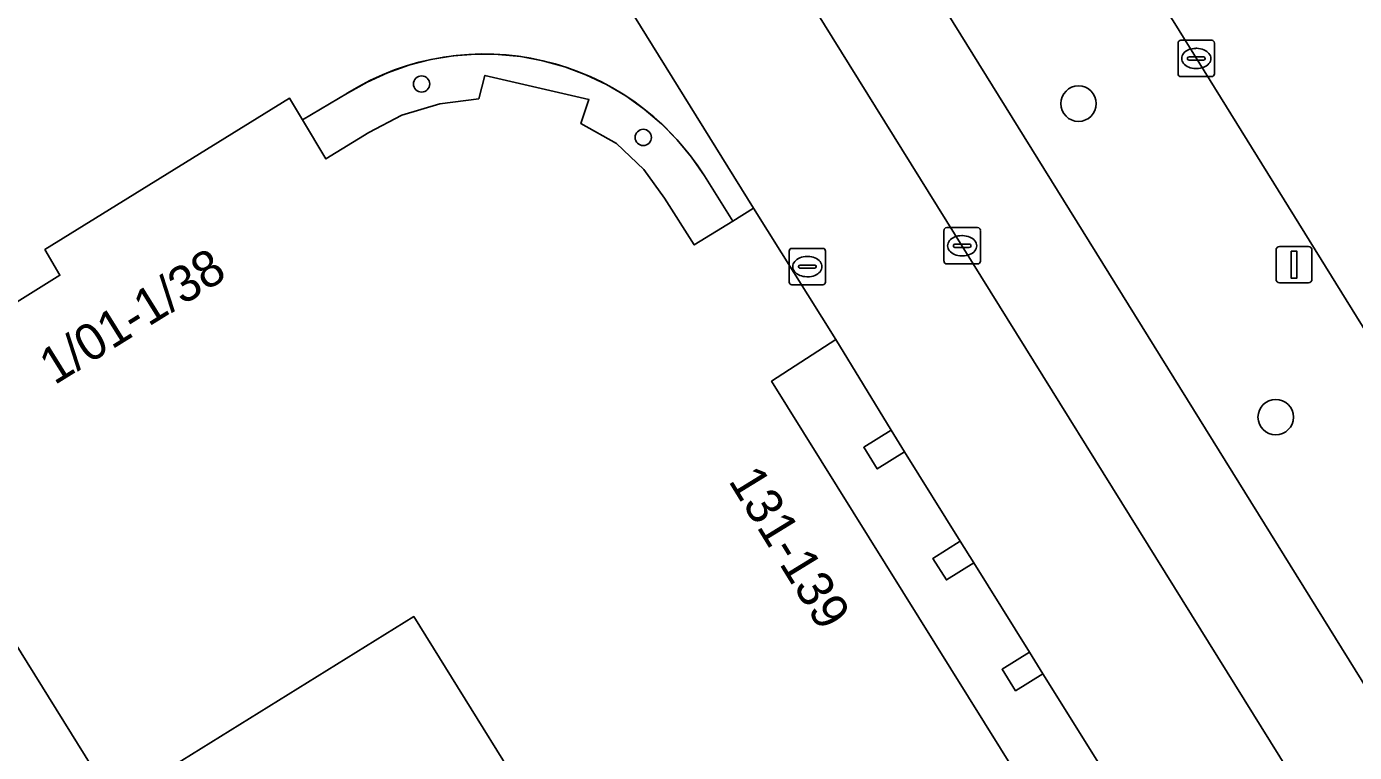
# Model space of a CAD drawing. Extents: x 160304 to 160955, y 383684 to 384161.
# Drawn here: x 160743.18 to 160779.74, y 384074.11 to 384094.11 of the extents above; entities that cross this region are included whole.
import ezdxf

# ---------------------------------------------------------------- set-up
doc = ezdxf.new("R2010")
doc.units = 0
for name, color, linetype in [('IMGEO_Boom', 7, 'Continuous'), ('IMGEO_Erf', 7, 'Continuous'), ('IMGEO_Fietspad_open', 7, 'Continuous'), ('IMGEO_Groenvoorziening', 7, 'Continuous'), ('IMGEO_Haag', 7, 'Continuous'), ('IMGEO_Kolk', 7, 'Continuous'), ('IMGEO_Lichtmast', 7, 'Continuous'), ('IMGEO_Pand', 7, 'Continuous'), ('IMGEO_Pand_nummerreeks', 7, 'Continuous'), ('IMGEO_Pand_overbouw', 7, 'Continuous'), ('IMGEO_Parkeervlak_open', 7, 'Continuous'), ('IMGEO_Rijbaan_lokaal_gesloten', 7, 'Continuous'), ('IMGEO_Rioolput', 7, 'Continuous'), ('IMGEO_Voetpad_open', 7, 'Continuous')]:
    doc.layers.add(name, color=color, linetype=linetype)

msp = doc.modelspace()

# ---------------------------------------------------------------- linework, layer by layer
at = {"layer": 'IMGEO_Boom'}
for centre in [(160772.146, 384091.984), (160777.574, 384083.35)]:
    msp.add_circle(centre, 0.489, dxfattribs=at)
at = {"layer": 'IMGEO_Erf'}
for points in [[(160755.635, 384092.12), (160755.804, 384092.759), (160758.666, 384092.1), (160758.445, 384091.436), (160759.426, 384090.887), (160760.175, 384090.166), (160760.744, 384089.38), (160761.566, 384088.092), (160762.626, 384088.748), (160761.845, 384089.993)], [(160752.016, 384092.274), (160750.778, 384091.538), (160751.426, 384090.46), (160752.611, 384091.192), (160753.516, 384091.667), (160754.563, 384091.979), (160755.635, 384092.12)], [(160772.696, 384073.832), (160771.166, 384076.282), (160770.412, 384075.813), (160770.041, 384076.406), (160770.795, 384076.876), (160769.262, 384079.336), (160768.508, 384078.866), (160768.136, 384079.46), (160768.891, 384079.93), (160767.358, 384082.395), (160766.603, 384081.925), (160766.233, 384082.519), (160766.987, 384082.989), (160765.464, 384085.483), (160763.696, 384084.339), (160772.246, 384070.611)], [(160762.238, 384064.34), (160753.846, 384077.856), (160745.599, 384072.736)]]:
    msp.add_lwpolyline(points, dxfattribs=at)
for centre, radius, start, end in [((160755.787, 384086.208), 7.143, 31.9983, 121.8712), ((160754.059, 384092.525), 0.224, 0, 180), ((160754.059, 384092.525), 0.224, 180, 0), ((160760.162, 384091.052), 0.224, 0, 180), ((160760.162, 384091.052), 0.224, 180, 0)]:
    msp.add_arc(centre, radius, start, end, dxfattribs=at)
at = {"layer": 'IMGEO_Fietspad_open'}
for points in [[(160751.873, 384115.337), (160755.715, 384109.34), (160755.728, 384109.32), (160788.518, 384056.578), (160823.662, 384000), (160830.017, 383989.77), (160839.554, 383974.387)], [(160842.328, 383975.591), (160832.842, 383990.888), (160827.177, 384000), (160814.975, 384019.629), (160813.456, 384022.072), (160805.259, 384035.309), (160768.526, 384094.486), (160764.835, 384100.432), (160758.942, 384109.926), (160757.079, 384112.871)]]:
    msp.add_lwpolyline(points, dxfattribs=at)
at = {"layer": 'IMGEO_Groenvoorziening'}
for points in [[(160786.766, 384074.88), (160774.746, 384094.262), (160772.522, 384097.674), (160768.7, 384103.329)], [(160768.526, 384094.486), (160805.259, 384035.309), (160806.841, 384036.335), (160804.538, 384041.052), (160799.23, 384052.134), (160793.098, 384064.312)]]:
    msp.add_lwpolyline(points, dxfattribs=at)
at = {"layer": 'IMGEO_Haag'}
for points in [[(160790.082, 384069.549), (160786.766, 384074.88), (160774.746, 384094.262), (160772.522, 384097.674), (160768.7, 384103.329)], [(160768.526, 384094.486), (160805.259, 384035.309), (160806.841, 384036.335), (160804.538, 384041.052), (160799.23, 384052.134), (160793.098, 384064.312)]]:
    msp.add_lwpolyline(points, dxfattribs=at)
at = {"layer": 'IMGEO_Kolk'}
for p, q in [((160774.885, 384092.801), (160774.885, 384093.653)), ((160774.96, 384093.727), (160775.812, 384093.727)), ((160775.373, 384093.507), (160775.398, 384093.507)), ((160775.886, 384093.653), (160775.886, 384092.801)), ((160775.144, 384093.221), (160775.144, 384093.233)), ((160775.582, 384093.184), (160775.184, 384093.184)), ((160775.187, 384093.27), (160775.585, 384093.27)), ((160775.628, 384093.233), (160775.628, 384093.221)), ((160775.812, 384092.727), (160774.96, 384092.727)), ((160775.396, 384092.947), (160775.371, 384092.947)), ((160768.441, 384087.642), (160768.441, 384088.494)), ((160768.516, 384088.568), (160769.368, 384088.568)), ((160768.929, 384088.348), (160768.954, 384088.348)), ((160769.442, 384088.494), (160769.442, 384087.642)), ((160768.7, 384088.062), (160768.7, 384088.074)), ((160769.138, 384088.025), (160768.74, 384088.025)), ((160768.743, 384088.111), (160769.141, 384088.111)), ((160769.184, 384088.074), (160769.184, 384088.062)), ((160768.952, 384087.788), (160768.927, 384087.788)), ((160769.368, 384087.568), (160768.516, 384087.568))]:
    msp.add_line(p, q, dxfattribs=at)
for points in [[(160774.885, 384092.801), (160774.885, 384093.653)], [(160774.96, 384093.727), (160775.812, 384093.727)], [(160775.886, 384093.653), (160775.886, 384092.801)], [(160775.812, 384092.727), (160774.96, 384092.727)], [(160768.441, 384087.642), (160768.441, 384088.494)], [(160768.516, 384088.568), (160769.368, 384088.568)], [(160769.442, 384088.494), (160769.442, 384087.642)], [(160769.368, 384087.568), (160768.516, 384087.568)]]:
    msp.add_lwpolyline(points, dxfattribs=at)
for centre, radius, start, end in [((160774.962, 384093.651), 0.0765, 91.552, 178.448), ((160774.962, 384093.651), 0.0765, 91.552, 178.448), ((160775.81, 384093.651), 0.0765, 1.552, 88.448), ((160775.81, 384093.651), 0.0765, 1.552, 88.448), ((160775.184, 384093.23), 0.0403, 85.8775, 175.7526), ((160775.181, 384093.22), 0.0366, 178.938, 274.7102), ((160775.585, 384093.227), 0.043, 264.8664, 352.4533), ((160775.589, 384093.232), 0.0386, 1.7309, 96.639), ((160774.962, 384092.803), 0.0765, 181.552, 268.448), ((160774.962, 384092.803), 0.0765, 181.552, 268.448), ((160775.81, 384092.803), 0.0765, 271.552, 358.448), ((160775.81, 384092.803), 0.0765, 271.552, 358.448), ((160768.518, 384088.492), 0.0765, 91.552, 178.448), ((160768.518, 384088.492), 0.0765, 91.552, 178.448), ((160769.366, 384088.492), 0.0765, 1.552, 88.448), ((160769.366, 384088.492), 0.0765, 1.552, 88.448), ((160768.74, 384088.071), 0.0403, 85.8775, 175.7526), ((160768.737, 384088.061), 0.0366, 178.938, 274.7102), ((160769.141, 384088.068), 0.043, 264.8664, 352.4533), ((160769.145, 384088.073), 0.0386, 1.7309, 96.639), ((160768.518, 384087.644), 0.0765, 181.552, 268.448), ((160768.518, 384087.644), 0.0765, 181.552, 268.448), ((160769.366, 384087.644), 0.0765, 271.552, 358.448), ((160769.366, 384087.644), 0.0765, 271.552, 358.448)]:
    msp.add_arc(centre, radius, start, end, dxfattribs=at)
for centre, major_axis, ratio, start_param, end_param in [((160775.372, 384093.227), (-0.387, 0.002), 0.722429, 4.712389, 7.853982), ((160775.397, 384093.227), (-0.39, 0.002), 0.717154, 1.570796, 4.712389), ((160768.928, 384088.068), (-0.387, 0.002), 0.722429, 4.712389, 7.853982), ((160768.953, 384088.068), (-0.39, 0.002), 0.717154, 1.570796, 4.712389)]:
    msp.add_ellipse(centre, major_axis=major_axis, ratio=ratio, start_param=start_param, end_param=end_param, dxfattribs=at)
at = {"layer": 'IMGEO_Lichtmast'}
for p, q in [((160777.682, 384088.048), (160778.472, 384088.048)), ((160778.472, 384088.048), (160777.682, 384088.048)), ((160777.582, 384087.148), (160777.582, 384087.948)), ((160777.582, 384087.948), (160777.582, 384087.148)), ((160778.572, 384087.948), (160778.572, 384087.148)), ((160778.572, 384087.148), (160778.572, 384087.948)), ((160778.472, 384087.048), (160777.682, 384087.048)), ((160777.682, 384087.048), (160778.472, 384087.048))]:
    msp.add_line(p, q, dxfattribs=at)
msp.add_lwpolyline([(160778.002, 384087.923), (160778.152, 384087.923), (160778.152, 384087.173), (160778.002, 384087.173), (160778.002, 384087.923)], dxfattribs=at)
for centre, start, end in [((160777.682, 384087.948), 90, 180), ((160777.682, 384087.948), 90, 180), ((160778.472, 384087.948), 0, 90), ((160778.472, 384087.948), 360, 90), ((160777.682, 384087.148), 180, 270), ((160777.682, 384087.148), 180, 270), ((160778.472, 384087.148), 270, 0), ((160778.472, 384087.148), 270, 0)]:
    msp.add_arc(centre, 0.1, start, end, dxfattribs=at)
at = {"layer": 'IMGEO_Pand'}
for points in [[(160772.246, 384070.611), (160763.696, 384084.339), (160765.464, 384085.483), (160763.201, 384089.104), (160762.626, 384088.748), (160761.566, 384088.092), (160760.744, 384089.38), (160760.175, 384090.166), (160759.426, 384090.887), (160758.445, 384091.436), (160758.666, 384092.1), (160755.804, 384092.759), (160755.635, 384092.12), (160754.563, 384091.979), (160753.516, 384091.667), (160752.611, 384091.192), (160751.426, 384090.46), (160750.778, 384091.538), (160750.419, 384092.135), (160743.69, 384087.966), (160744.105, 384087.258), (160741.673, 384085.744)], [(160738.24, 384084.566), (160745.599, 384072.736), (160753.846, 384077.856), (160762.238, 384064.34)]]:
    msp.add_lwpolyline(points, dxfattribs=at)
for points in [[(160745.599, 384072.736), (160738.24, 384084.566), (160723.825, 384075.6), (160724.675, 384074.255), (160723.472, 384073.526), (160722.622, 384074.871), (160718.989, 384072.622), (160720.124, 384070.796), (160714.211, 384067.125), (160715.145, 384065.622), (160713.123, 384064.367), (160726.004, 384043.621), (160733.056, 384047.999), (160737.814, 384050.953), (160730.219, 384063.187)], [(160766.987, 384082.989), (160766.233, 384082.519), (160766.603, 384081.925), (160767.358, 384082.395)], [(160768.891, 384079.93), (160768.136, 384079.46), (160768.508, 384078.866), (160769.262, 384079.336)], [(160770.795, 384076.876), (160770.041, 384076.406), (160770.412, 384075.813), (160771.166, 384076.282)]]:
    msp.add_lwpolyline(points, close=True, dxfattribs=at)
for centre, start, end in [((160754.059, 384092.525), 0, 180), ((160754.059, 384092.525), 180, 0), ((160760.162, 384091.052), 0, 180), ((160760.162, 384091.052), 180, 0)]:
    msp.add_arc(centre, 0.224, start, end, dxfattribs=at)
at = {"layer": 'IMGEO_Pand_overbouw'}
for points in [[(160760.661, 384091.43), (160760.188, 384091.834), (160759.682, 384092.196), (160759.146, 384092.512), (160758.584, 384092.781), (160758.002, 384092.999), (160757.402, 384093.166), (160756.79, 384093.28), (160756.171, 384093.341), (160755.549, 384093.347), (160754.929, 384093.299), (160754.315, 384093.197), (160753.712, 384093.043), (160753.125, 384092.836), (160752.558, 384092.579), (160752.016, 384092.274), (160750.778, 384091.538), (160751.426, 384090.46), (160752.611, 384091.192), (160753.516, 384091.667), (160754.563, 384091.979), (160755.635, 384092.12), (160755.804, 384092.759), (160758.666, 384092.1), (160758.445, 384091.436), (160759.426, 384090.887), (160760.175, 384090.166), (160760.744, 384089.38), (160761.566, 384088.092), (160762.626, 384088.748), (160761.845, 384089.993), (160761.493, 384090.506), (160761.097, 384090.986)], [(160769.262, 384079.336), (160768.508, 384078.866), (160768.136, 384079.46), (160768.891, 384079.93), (160767.358, 384082.395), (160766.603, 384081.925), (160766.233, 384082.519), (160766.987, 384082.989), (160765.464, 384085.483), (160763.696, 384084.339), (160772.246, 384070.611), (160773.241, 384071.279), (160772.903, 384071.823), (160773.657, 384072.292), (160773.067, 384073.238), (160772.312, 384072.769), (160771.941, 384073.363), (160772.696, 384073.832), (160771.166, 384076.282), (160770.412, 384075.813), (160770.041, 384076.406), (160770.795, 384076.876)]]:
    msp.add_lwpolyline(points, close=True, dxfattribs=at)
at = {"layer": 'IMGEO_Parkeervlak_open'}
for points in [[(160761.845, 384089.993), (160762.626, 384088.748), (160763.201, 384089.104), (160755.07, 384102.215), (160707.989, 384073.011), (160711.21, 384067.807), (160718.989, 384072.622), (160722.622, 384074.871), (160723.472, 384073.526), (160724.675, 384074.255), (160723.825, 384075.6), (160738.24, 384084.566)], [(160738.24, 384084.566), (160741.223, 384086.421), (160741.673, 384085.744), (160744.105, 384087.258), (160743.69, 384087.966), (160750.419, 384092.135), (160750.778, 384091.538), (160752.016, 384092.274)]]:
    msp.add_lwpolyline(points, dxfattribs=at)
msp.add_arc((160755.787, 384086.208), 7.143, 31.9983, 121.8712, dxfattribs=at)
at = {"layer": 'IMGEO_Rijbaan_lokaal_gesloten'}
msp.add_lwpolyline([(160777.428, 384098.352), (160775.75, 384100.796), (160766.365, 384114.473), (160762.643, 384112.202), (160764.513, 384109.525), (160765.165, 384108.56), (160768.7, 384103.329), (160772.522, 384097.674), (160774.746, 384094.262), (160786.766, 384074.88), (160790.082, 384069.549)], dxfattribs=at)
at = {"layer": 'IMGEO_Rioolput'}
for p, q in [((160764.254, 384087.995), (160765.106, 384087.995)), ((160764.179, 384087.069), (160764.179, 384087.921)), ((160764.667, 384087.775), (160764.692, 384087.775)), ((160765.18, 384087.921), (160765.18, 384087.069)), ((160764.438, 384087.489), (160764.438, 384087.501)), ((160764.876, 384087.452), (160764.478, 384087.452)), ((160764.481, 384087.538), (160764.879, 384087.538)), ((160764.922, 384087.501), (160764.922, 384087.489)), ((160765.106, 384086.995), (160764.254, 384086.995)), ((160764.69, 384087.215), (160764.665, 384087.215))]:
    msp.add_line(p, q, dxfattribs=at)
for points in [[(160764.254, 384087.995), (160765.106, 384087.995)], [(160764.179, 384087.069), (160764.179, 384087.921)], [(160765.18, 384087.921), (160765.18, 384087.069)], [(160765.106, 384086.995), (160764.254, 384086.995)]]:
    msp.add_lwpolyline(points, dxfattribs=at)
for centre, radius, start, end in [((160764.256, 384087.919), 0.0765, 91.552, 178.448), ((160764.256, 384087.919), 0.0765, 91.552, 178.448), ((160765.104, 384087.919), 0.0765, 1.552, 88.448), ((160765.104, 384087.919), 0.0765, 1.552, 88.448), ((160764.478, 384087.498), 0.0403, 85.8775, 175.7526), ((160764.475, 384087.488), 0.0366, 178.938, 274.7102), ((160764.879, 384087.495), 0.043, 264.8664, 352.4533), ((160764.883, 384087.5), 0.0386, 1.7309, 96.639), ((160764.256, 384087.071), 0.0765, 181.552, 268.448), ((160764.256, 384087.071), 0.0765, 181.552, 268.448), ((160765.104, 384087.071), 0.0765, 271.552, 358.448), ((160765.104, 384087.071), 0.0765, 271.552, 358.448)]:
    msp.add_arc(centre, radius, start, end, dxfattribs=at)
for centre, major_axis, ratio, start_param, end_param in [((160764.666, 384087.495), (-0.387, 0.002), 0.722429, 4.712389, 7.853982), ((160764.691, 384087.495), (-0.39, 0.002), 0.717154, 1.570796, 4.712389)]:
    msp.add_ellipse(centre, major_axis=major_axis, ratio=ratio, start_param=start_param, end_param=end_param, dxfattribs=at)
at = {"layer": 'IMGEO_Voetpad_open'}
for points in [[(160748.766, 384112.379), (160751.559, 384107.876), (160751.853, 384107.403), (160755.07, 384102.215), (160763.201, 384089.104), (160765.464, 384085.483), (160766.987, 384082.989), (160767.358, 384082.395), (160768.891, 384079.93), (160769.262, 384079.336), (160770.795, 384076.876), (160771.166, 384076.282), (160772.696, 384073.832), (160773.067, 384073.238), (160773.657, 384072.292), (160774.008, 384071.729), (160774.908, 384070.284), (160775.123, 384069.937), (160776.223, 384070.629), (160791.968, 384044.989)], [(160830.017, 383989.77), (160823.662, 384000), (160788.518, 384056.578), (160755.728, 384109.32), (160755.715, 384109.34)]]:
    msp.add_lwpolyline(points, dxfattribs=at)

# ---------------------------------------------------------------- texts
at = {"layer": 'IMGEO_Pand_nummerreeks'}
for s, rotation, p in [('1/01-1/38', 31.9023, (160743.952, 384084.219)), ('131-139', 301.5698, (160762.489, 384081.597))]:
    msp.add_text(s, height=1, rotation=rotation, dxfattribs=at).set_placement(p)

doc.saveas('drawing.dxf')
